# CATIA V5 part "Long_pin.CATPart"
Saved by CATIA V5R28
Part number: Long_pin
Material "Vert clair": density 7860 kg/m3, Young's modulus 2e+11 Pa, Poisson ratio 0.266
Bounding box of the stored display mesh (mm): x -25 to 25, y -24.818 to 24.818, z 0 to 140
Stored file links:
  E:\Back up\Mission d'enseignement\TP Catia\2 oct - Assemblage\Long_pin.CATPart
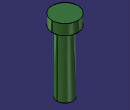
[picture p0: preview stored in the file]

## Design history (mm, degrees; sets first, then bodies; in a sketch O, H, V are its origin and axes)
Body1 (main body), material "Vert clair"
  Sketch1 on xy-plane, origin (0, 0, 0), H (1, 0, 0), V (0, 1, 0)
    circle A1 centre (0, 0) radius 15
    radius A1 = 15
  Pad1: profile Sketch1, direction (0, 0, 1), length 120
  Sketch2 on end face of Pad1, origin (0, 0, 120), H (1, 0, 0), V (0, 1, 0)
    circle A1 centre (0, 0) radius 25
    radius A1 = 25
  Pad2: profile Sketch2, direction (0, 0, 1), length 20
